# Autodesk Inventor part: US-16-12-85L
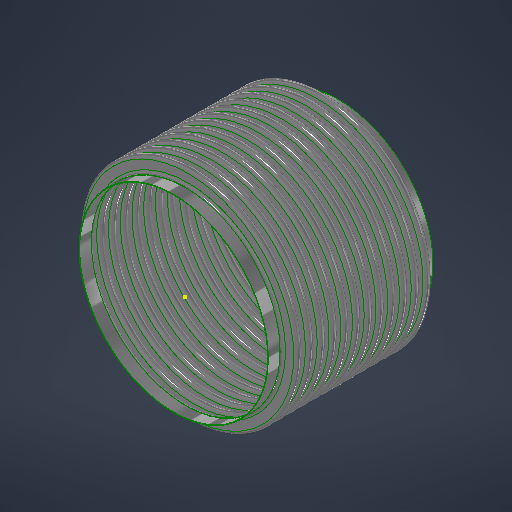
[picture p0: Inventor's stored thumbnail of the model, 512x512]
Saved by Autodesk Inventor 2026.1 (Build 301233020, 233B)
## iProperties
Category: 18 GA (0.048 THICK)
RuleStatus: InUse
Created: 2026-07
Part Number: US-16-12-85L
Project: =STOCK BELLOWS: <Stock Number><SFILL>
Material: ASTM A240-304
Description: =STOCK BELLOWS: <Stock Number>, <SID_> I.D., <SOD_> O.D., <SPLY_> PLY, <Category>, <SNET_CONS> CONS.<PITCH_><STANGENT_> TANGENT<SFILL>
Document SubType Name: Sheet Metal
Designer: LC
Stock Number: U.S-16-12-85L
Surface Area: 659.127 cm^2
Volume: 56.61 cm^3
Sheet Metal Rule: Default
Appearance: STAINLESS STEEL
NET_TUBE: 3.428
COUNTER: 1.500
PBAR: 1.214
PSET: 5.356
PLY: 2
CONS: 2
THK: 0.036
ID: 4.500
OD: 5.500
CONS_: 2
TANGENT: 0.500
PITCH: 0.375
BELLOWS_UPSET: 0.000
NET_CONS: 2
S_CONS: 0
Description_Units: 0
ID_M: 114.30 mm
OD_M: 139.70 mm
THK_M: 0.91 mm
ID_U: 4.500 in
OD_U: 5.500 in
THK_U: 0.036 in
TANGENT2: 0.500
d79: 1.000
d82: 1.000
d83: 26.000
d84: 24.000
d80: 2.571
d81: 10
SID: 2.375
SCONS_: 12
SPITCH: 0.250
SBELLOWS_UPSET: 0.000
SNET_CONS: 12
SS_CONS: 0
SCONS: 8
d174: 8
d177: 0.018
d178: 2.375
d179: 3.000
d180: 0.375
d181: 1.000
d182: 0.000
d190: 8
d191: 1
d192: 1
d193: 8
d194: 0
PART_NUMBER: U.S-16-12-85L
PRESSURE: 85
SIZE: 16.00
STANGENT_: 1.000
d214: 8
d217: 0.030
d218: 6.625
d219: 8.125
d220: 0.500
d221: 1.000
d222: 0.000
d230: 8
d231: 1
d232: 1
d233: 8
d234: 0
STANGENT: 4.000
SPLY_: 1
STHK_: 0.048
SID_: 16.000
SOD_: 18.500
SPITCH_: 1.000
STANGENT__: 1.000
SBELLOWS_UPSET_: 0.000
SDIFF_TAN: 1.000
TAN_TO_TAN: 0.750 in
d252: 2
d275: 2
d287: 0.050
d289: 0.500
d290: 0.000
d263: 2
d265: 1
d268: 2
d269: 0
d286: 2
d288: 1
d291: 2
d292: 0
SOD_NECK: 16 1/8
CFILL: .
SFILL: .
PITCH_: =, <SPITCH_> PITCH,
SREROLL: 0.750
MATTABLE: 20 GA (0.036 THICK)
MESH: ,
CSECT: 2
Author: LC
Keywords: 20 GA (0.036 THICK)
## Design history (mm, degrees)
sketch "Sketch2"
  geometry: L1 (0, -183.595)-(0, 600.956) reference; L2 (58.979, 0)-(57.15, 0); L3 (60.446, -1.467)-(66.554, -1.467); L4 (60.446, -3.296)-(66.554, -3.296); L5 (66.554, -8.058)-(60.446, -8.058); L6 (66.554, -6.229)-(60.446, -6.229); L7 (58.979, -9.525)-(57.15, -9.525); L8 (60.446, 0)-(60.446, -9.525); L9 (66.554, -4.762)-(69.85, -4.763); L10 (57.15, 0)-(57.15, -9.525); L11 (20.376, 102.841)-(20.376, 101.926); L12 (58.262, 488.877)-(58.262, 349.177); L13 (58.262, 479.352)-(58.262, 339.652); L14 (93.133, -58.817)-(93.133, -71.517); L15 (118.746, -66.401)-(118.746, -66.401); L16 (66.554, -6.229)-(66.554, -8.058); L17 (60.446, -6.229)-(60.446, -8.058); L18 (60.446, -7.144)-(66.554, -7.144); L19 (69.85, 0)-(69.85, -9.525); L20 (-66.554, -6.229)-(-66.554, -8.058); L21 (-66.554, -1.467)-(-60.446, -1.467); L22 (-66.554, -3.296)-(-60.446, -3.296); L23 (-60.446, -6.229)-(-66.554, -6.229); L24 (-66.554, -7.144)-(-60.446, -7.144); L25 (-60.446, -8.058)-(-66.554, -8.058); L26 (-60.446, -6.229)-(-60.446, -8.058); L27 (-57.15, -2.522)-(-57.15, -12.047); L28 (-60.446, -4.763)-(-57.15, -4.763); L29 (-66.554, 3.828)-(-66.554, -9.525); L30 (-68.021, 0)-(-69.85, 0); L31 (-69.85, 0)-(-69.85, -9.525); L32 (-68.021, -9.525)-(-69.85, -9.525); A1 r 1.467 centre (60.446, 0) between (58.979, 0) and (60.446, -1.467); A2 r 3.296 centre (60.446, 0) between (57.15, 0) and (60.446, -3.296); A3 r 3.296 centre (66.554, -4.762) between (66.554, -8.058) and (66.554, -1.467); A4 r 1.467 centre (66.554, -4.762) between (66.554, -6.229) and (66.554, -3.296); A5 r 1.467 centre (60.446, -9.525) between (60.446, -8.058) and (58.979, -9.525); A6 r 3.296 centre (60.446, -9.525) between (60.446, -6.229) and (57.15, -9.525); A7 r 2.381 centre (66.554, -4.762) between (66.554, -7.144) and (68.936, -4.762); A8 r 2.381 centre (60.446, -9.525) between (60.446, -7.144) and (58.064, -9.525); A9 r 1.467 centre (-66.554, -9.525) between (-66.554, -8.058) and (-68.021, -9.525); A10 r 1.467 centre (-60.446, -4.763) between (-60.446, -6.229) and (-60.446, -3.296); A11 r 2.381 centre (-60.446, -4.763) between (-60.446, -7.144) and (-58.064, -4.763); A12 r 3.296 centre (-60.446, -4.763) between (-60.446, -8.058) and (-60.446, -1.467); A13 r 2.381 centre (-66.554, -9.525) between (-66.554, -7.144) and (-68.936, -9.525); A14 r 3.296 centre (-66.554, -9.525) between (-66.554, -6.229) and (-69.85, -9.525); A15 r 1.467 centre (-66.554, 0) between (-68.021, 0) and (-66.554, -1.467); A16 r 3.296 centre (-66.554, 0) between (-69.85, 0) and (-66.554, -3.296); 10 further points
  constraints: 62 end point, 38 point on circle, 20 tangent, 16 centre point, 12 parallel, 9 midpoint, 7 vertical, 6 coincident, 6 concentric, 6 point on line, 4 equal radius, 4 perpendicular, 3 horizontal, 1 collinear, 1 horizontal alignment, 10 other
  dimensions: "THK" = 0.9144 distance of L11.start L11.end; "ID" = 114.3 distance of L11.end point (20.376, -12.374); "OD" = 139.7 distance of L12.start L12.end; "PITCH" = 9.525 distance of L12.start L13.start; "TANGENT" = 12.7 distance of L14.start L14.end; "BELLOWS_UPSET" = 0 distance of L15.start L15.end; "d43" = 114.3 diameter of L10 L1 (= ID); "d44" = 139.7 diameter of L9.end L1 (= OD); "d45" = 1.8288 distance between parallel lines of L5 L6 (computed from THK, PLY); "d46" = 3.29565 radius of A3 (computed from PITCH, THK, PLY); "UPSET_PITCH" = 9.525 distance of L2.end L7.end (derived); "SIDEWALL_ANGLE" = 0 deg angle of L3 L9 (derived); "CON_GAP" = 2.9337 distance of point (60.446, -6.229) point (60.446, -3.296) (derived); "TAN1" = 3.74046 dimension on A8 (derived); "TAN2" = 3.74046 dimension on A7 (derived); "LEG1" = 6.1087 distance of L18.start L18.end (derived); "d278" = 1.8288 distance between parallel lines of L25 L23 (derived); "d279" = 3.29565 radius of A12 (derived); "d280" = 9.525 distance of L30.end L31.end (derived); "d281" = 360 deg dimension on L21 L28 (derived); "d282" = 2.9337 distance of point (-66.554, -6.229) point (-66.554, -3.296) (derived); "d283" = 3.74046 dimension on A13 (derived); "d284" = 3.74046 dimension on A11 (derived); "d285" = 6.1087 distance of L24.start L24.end (derived); "d293" = 114.3 diameter of L27 L1 (derived); "d294" = 139.7 diameter of L31 L1 (derived)
  node "Sketch Rectangular Pattern1" dims "d31" = 25.4, "ID" = 114.3
  node "Sketch Rectangular Pattern2" dims "d39" = 25.4, "PITCH" = 9.525
revolve "CONS" stored, may be unused: angle "d48" = 90 deg
node "BELLOW MIDPLANE"
pattern_linear "Rectangular Pattern2" dims "d52" = 9.525 (= UPSET_PITCH)
sketch "Sketch5"
  geometry: C1 r 58.979 at (0, 0) reference; C2 r 57.15 at (0, 0) reference
extrude "TANGENT" new body sketch "Sketch5" distance "d53" = 12.7 (= TANGENT); taper "d54" = 0 deg
revolve "SAMETAN" stored, may be unused: angle "d65" = 90 deg
revolve "DIFFTAN" stored, may be unused: angle "d70" = 90 deg
sketch "Sketch9"
  geometry: L1 (58.391, 0)-(-58.391, 0) reference; L2 (0, -17.78)-(0, 17.78) reference; L3 (41.708, 0)-(-41.708, 0); L4 (41.708, -11.906)-(41.708, 11.906); L5 (29.008, -11.906)-(29.008, 11.906); L6 (15.418, 11.906)-(15.418, -11.906); L7 (-29.008, -11.906)-(-29.008, 11.906); L8 (-41.708, -11.906)-(-41.708, 11.906); L9 (40.914, -11.906)-(40.914, 11.906); L10 (41.708, -11.906)-(40.914, -11.906); L11 (41.708, 11.906)-(40.914, 11.906); L12 (15.815, 11.906)-(15.022, 11.906); L13 (15.022, 11.906)-(15.022, -11.906); L14 (15.022, -11.906)-(15.815, -11.906); L15 (15.815, -11.906)-(15.815, 11.906); L16 (-15.815, 11.906)-(-15.815, -11.906); L17 (-15.418, 11.906)-(-15.418, -11.906); L18 (-15.815, -11.906)-(-15.022, -11.906); L19 (-15.022, -11.906)-(-15.022, 11.906); L20 (-15.022, 11.906)-(-15.815, 11.906); L21 (-41.708, -11.906)-(-40.914, -11.906); L22 (-40.914, -11.906)-(-40.914, 11.906); L23 (-40.914, 11.906)-(-41.708, 11.906); L24 (-41.708, 11.906)-(-41.708, -11.906); L25 (41.708, -0.397)-(-41.708, -0.397); L26 (-41.708, -0.397)-(-41.708, 0.397); L27 (-41.708, 0.397)-(41.708, 0.397); L28 (41.708, 0.397)-(41.708, -0.397); L29 (-41.708, 11.906)-(41.708, 11.906); L30 (41.708, 11.906)-(41.708, 12.7); L31 (41.708, 12.7)-(-41.708, 12.7); L32 (-41.708, 12.7)-(-41.708, 11.906); L33 (41.708, -11.906)-(-41.708, -11.906); L34 (-41.708, -11.906)-(-41.708, -12.7); L35 (-41.708, -12.7)-(41.708, -12.7); L36 (41.708, -12.7)-(41.708, -11.906); 30 further points
  constraints: 68 end point, 13 midpoint, 13 parallel, 8 horizontal, 7 perpendicular, 6 equal length, 3 point on line, 2 vertical, 14 other
  dimensions: "d115" = 23.8125 distance of L4.start L4.end (derived); "d116" = 12.7 distance between parallel lines of L4 L5 (derived); "d117" = 13.58962 distance between parallel lines of L5 L6 (derived); "d125" = 44.42645 distance between parallel lines of L7 L6 (derived); "d127" = 12.7 distance between parallel lines of L8 L7 (derived); "d128" = 26.28962 distance between parallel lines of L6 L4 (derived); "d130" = 83.41607 distance between parallel lines of L8 L4 (derived); "RULER_THK" = 0.79375 distance between parallel lines of L4 L9; "d135" = 0.79375 distance of L13.end L14.end (derived); "d138" = 30.83684 distance of L13.end L16.end (derived); "d143" = 0.79375 distance of L22.end L8.end (derived); "d144" = 0.79375 distance between parallel lines of L27 L25 (derived)
extrude "RULER" join sketch "Sketch9" distance "d149" = 0.79375 (derived); taper "d150" = 0 deg
extrude "BARS" join sketch "Sketch9" distance "d151" = 0.79375 (derived); taper "d152" = 0 deg
pattern_linear "Rectangular Pattern4" dims "d155" = 30.83684 (derived)
sketch "Sketch13"
  geometry: L1 (93.149, -52.467)-(93.149, -77.867); L2 (204.419, 0)-(203.2, 0); L3 (204.419, -25.4)-(203.2, -25.4); L4 (227.99, -19.66)-(210.16, -19.66); L5 (227.99, -18.44)-(210.16, -18.44); L6 (227.99, -12.7)-(234.95, -12.7); L7 (210.16, -5.74)-(227.99, -5.74); L8 (210.16, 0)-(210.16, -25.4); L9 (203.2, 0)-(203.2, -25.4); L10 (58.254, -237.139)-(58.254, -707.039); L11 (58.254, -262.539)-(58.254, -732.439); L12 (58.254, -313.339)-(58.254, -783.239); L13 (58.254, -338.739)-(58.254, -808.639); L14 (58.254, -364.139)-(58.254, -834.039); L15 (58.254, -389.539)-(58.254, -859.439); L16 (58.254, -414.939)-(58.254, -884.839); L17 (58.254, -287.939)-(58.254, -757.839); L18 (20.376, 103.145)-(20.376, 101.926); L19 (210.16, -6.96)-(227.99, -6.96); L20 (0, -1034.115)-(0, 292.333) reference; L21 (-40.958, 0)-(245.745, 0) reference; A1 r 5.74 centre (210.16, 0) between (204.419, 0) and (210.16, -5.74); A2 r 5.74 centre (210.16, -25.4) between (210.16, -19.66) and (204.419, -25.4); A3 r 6.96 centre (210.16, -25.4) between (210.16, -18.44) and (203.2, -25.4); A4 r 5.74 centre (227.99, -12.7) between (227.99, -18.44) and (227.99, -6.96); A5 r 6.96 centre (227.99, -12.7) between (227.99, -19.66) and (227.99, -5.74); A6 r 6.96 centre (210.16, 0) between (203.2, 0) and (210.16, -6.96); 6 further points; 1 other entity
  constraints: 38 end point, 15 point on circle, 9 tangent, 6 centre point, 6 parallel, 5 vertical alignment, 4 point on line, 4 vertical, 3 coincident, 3 concentric, 2 collinear, 2 equal radius, 1 horizontal, 1 perpendicular, 23 other
  dimensions: "SBELLOWS_UPSET_" = 0 distance of point (118.762, -66.401) point (118.762, -66.401); "STOTAL_THK_BELLOW__" = 1.2192 distance between parallel lines of L4 L5 (derived); "d224" = 6.9596 radius of A5 (derived); "d225" = 25.4 distance of L2.end L3.end (derived); "SSIDEWALL_ANGLE_" = 0 deg angle of L7 L6 (derived); "SSCON_GAP_" = 11.4808 distance of point (210.16, -18.44) point (210.16, -6.96) (derived); "d235" = 406.4 diameter of L9 L20 (derived); "d236" = 469.9 diameter of L6.end L20 (derived)
  node "Sketch Rectangular Pattern4" dims "d228" = 25.4
  node "Sketch Rectangular Pattern5" dims "d229" = 25.4
revolve "SBELLOW" stored, may be unused: angle "d197" = 90 deg
pattern_linear "Rectangular Pattern5" dims "d204" = 25.4 (derived)
revolve "STANGENT" stored, may be unused: angle "d240" = 90 deg
revolve "SSAMETAN" stored, may be unused: angle "d241" = 90 deg
revolve "SDIFFTAN" stored, may be unused: angle "d246" = 90 deg
revolve "INVCON" stored, may be unused: angle "d295" = 90 deg
pattern_linear "Rectangular Pattern6" dims "d298" = 9.525 (derived)
revolve "INVTANGENT" stored, may be unused: angle "d302" = 90 deg
revolve "INVSAMETAN" stored, may be unused: angle "d307" = 90 deg
revolve "INVDIFFTAN" stored, may be unused: angle "d312" = 90 deg
sketch "ID BELLOW MOUNT CALC"
  geometry: L1 (44.45, 0)-(38.1, 0); L2 (38.1, 0)-(38.1, 12.7); L3 (38.1, 12.7)-(44.45, 12.7); L4 (44.45, 12.7)-(44.45, 0); L5 (36.513, 12.7)-(34.684, 12.7); L6 (34.684, 12.7)-(34.684, 0); L7 (34.684, 0)-(36.513, 0); L8 (36.513, 0)-(36.513, 12.7); L9 (0, -2.54)-(0, 15.24) reference; L10 (-8.89, 0)-(53.34, 0) reference; 1 further point
  constraints: 16 end point, 5 parallel, 2 collinear, 2 horizontal, 2 perpendicular
  dimensions: "d314" = 12.7 distance of L5.end L6.end (derived); "d315" = 1.8288 distance of L5.start L5.end (derived); "IG" = 1.5875 distance between parallel lines of L2 L8; "PIPE_OD" = 88.9 diameter of L4 L9; "PIPE_WALL" = 6.35 distance of L2.end L3.end; "ID_MT_BELLOW" = 69.3674 diameter of L6 L9 (derived)
revolve "CFILL" stored, may be unused: angle "d320" = 90 deg
pattern_linear "Rectangular Pattern7" dims "d323" = 9.525 (derived)
revolve "SFILL" stored, may be unused: angle "d324" = 90 deg
pattern_linear "Rectangular Pattern8" dims "d327" = 25.4 (derived)
node "STOCK BELLOW MIDPLANE"
sketch "Sketch21"
  geometry: L1 (0, -100.013)-(0, 100.013) reference; L2 (-100.013, 0)-(100.013, 0) reference; L3 (-0.099, 71.437)-(0.099, 71.437); L4 (0.099, 71.437)-(0.099, 55.562); L5 (0.099, 55.562)-(-0.099, 55.562); L6 (-0.099, 55.562)-(-0.099, 71.437); C1 r 55.562 at (0, 0); C2 r 71.437 at (0, 0); 3 further points
  constraints: 8 end point, 2 centre point, 2 coincident, 2 parallel, 2 tangent, 1 horizontal, 1 perpendicular, 1 other
  dimensions: "d329" = 111.125 diameter of C1 (derived); "d330" = 142.875 diameter of C2 (derived); "d331" = 0.19844 distance of L3.start L3.end
extrude "CLAMSHELL" cut sketch "Sketch21" extent not by distance; stored distance "d332" = 0; taper "d333" = 0 deg
pattern_circular "Circular Pattern1" dims angle "d335" = 180 deg (derived)
node "BELLOW"
sketch "Sketch6"
  geometry: L1 (-19.05, 58.979)-(-6.35, 58.979); L2 (-6.35, 58.979)-(-6.35, 57.15); L3 (-6.35, 57.15)-(-19.05, 57.15); L4 (-19.05, 57.15)-(-19.05, 58.979); L5 (2.54, 0)-(-59.69, 0) reference; L6 (-38.1, -108.388)-(-38.1, 156.601) reference; 1 further point
  constraints: 8 end point, 2 parallel, 1 horizontal, 1 perpendicular
  dimensions: "d61" = 12.7 distance of L2.end L3.end (derived); "d62" = 1.8288 distance of L1.end L2.end (derived); "d63" = 114.3 diameter of L3 L5 (derived); "d64" = 19.05 distance between parallel lines of L4 L6 (derived)
sketch "Sketch12"
  geometry: 1 further point
sketch "Sketch14"
  geometry: L1 (-25.4, 204.419)-(0, 204.419); L2 (0, 204.419)-(0, 203.2); L3 (0, 203.2)-(-25.4, 203.2); L4 (-25.4, 203.2)-(-25.4, 204.419); L5 (5.08, 0)-(-30.48, 0) reference; L6 (0, -35.743)-(0, 214.457) reference; 1 further point
  constraints: 8 end point, 2 parallel, 1 collinear, 1 horizontal, 1 perpendicular
  dimensions: "d237" = 1.2192 distance of L3.end L1.start (derived); "d238" = 406.4 diameter of L3 L5 (derived); "d239" = 25.4 distance of L1.start L1.end (derived); "SOD_NECK" = 408.8384 diameter of L1 L5 (derived)
sketch "Sketch15"
  geometry: L1 (-35.743, 0)-(214.457, 0) reference; L2 (203.2, -304.8)-(204.419, -304.8); L3 (204.419, -304.8)-(204.419, -330.2); L4 (204.419, -330.2)-(203.2, -330.2); L5 (203.2, -330.2)-(203.2, -304.8); L6 (0, -398.78)-(0, 81.28) reference; 1 further point
  constraints: 8 end point, 2 parallel, 1 horizontal, 1 perpendicular
  dimensions: "d205" = 25.4 distance of L4.end L2.start (derived); "d206" = 1.2192 distance of L3.end L4.end (derived); "d207" = 406.4 diameter of L5 L6 (derived); "d208" = 304.8 distance between parallel lines of L1 L2 (derived)
node "TANGENT_"
node "SAME_TAN"
sketch "Sketch8"
  geometry: L1 (58.979, -19.05)-(57.15, -19.05); L2 (57.15, -19.05)-(57.15, -31.75); L3 (57.15, -31.75)-(58.979, -31.75); L4 (58.979, -31.75)-(58.979, -19.05); L5 (0, -40.64)-(0, 21.59) reference; L6 (-108.388, 0)-(156.601, 0) reference; 1 further point
  constraints: 8 end point, 2 parallel, 1 horizontal, 1 perpendicular
  dimensions: "d66" = 114.3 diameter of L2 L5 (derived); "TOTAL_THK_BELLOW" = 1.8288 distance of L2.end L3.end (derived); "d68" = 19.05 distance between parallel lines of L1 L6 (derived); "d69" = 12.7 distance of L1.end L2.end (derived)
node "DIFF_TAN"
node "Sketch Rectangular Pattern3" dims "d138" = 30.83684 (derived), "d141" = 25.4
node "SBELLOW_"
node "STANGENT_"
node "SSAME_TAN"
sketch "Sketch16"
  geometry: L1 (204.419, -304.8)-(203.2, -304.8); L2 (203.2, -304.8)-(203.2, -330.2); L3 (203.2, -330.2)-(204.419, -330.2); L4 (204.419, -330.2)-(204.419, -304.8); L5 (0, -398.78)-(0, 81.28) reference; L6 (-35.743, 0)-(214.457, 0) reference; 1 further point
  constraints: 8 end point, 2 parallel, 1 horizontal, 1 perpendicular
  dimensions: "SDIFF_TAN" = 25.4 distance of L3.end L1.start; "d243" = 1.2192 distance of L2.end L3.end (derived); "d244" = 304.8 distance between parallel lines of L1 L6 (derived); "d245" = 406.4 diameter of L2 L5 (derived)
node "SDIFF_TAN"
body "Solid15"
sketch "Sketch17"
  geometry: L1 (69.85, 12.7)-(68.021, 12.7); L2 (68.021, 12.7)-(68.021, 0); L3 (68.021, 0)-(69.85, 0); L4 (69.85, 0)-(69.85, 12.7); L5 (0, -2.54)-(0, 15.24) reference; L6 (-13.97, 0)-(83.82, 0) reference; 2 further points
  constraints: 8 end point, 2 parallel, 1 horizontal, 1 midpoint, 1 perpendicular, 1 point on line
  dimensions: "INVTANGENT" = 12.7 distance of L3.end L1.start (derived); "d300" = 1.8288 distance of L1.start L1.end (derived); "d301" = 139.7 diameter of L4 L5 (derived)
body "Solid16"
sketch "Sketch18"
  geometry: L1 (69.85, -19.05)-(68.021, -19.05); L2 (68.021, -19.05)-(68.021, -31.75); L3 (68.021, -31.75)-(69.85, -31.75); L4 (69.85, -31.75)-(69.85, -19.05); L5 (-13.97, 0)-(83.82, 0) reference; L6 (0, -40.64)-(0, 21.59) reference; 1 further point
  constraints: 8 end point, 2 parallel, 1 horizontal, 1 perpendicular
  dimensions: "d303" = 19.05 distance between parallel lines of L1 L5 (derived); "d304" = 12.7 distance of L3.end L1.start (derived); "d305" = 1.8288 distance of L2.end L3.end (derived); "d306" = 139.7 diameter of L4 L6 (derived)
body "Solid17"
sketch "Sketch19"
  geometry: L1 (69.85, -19.05)-(68.021, -19.05); L2 (68.021, -19.05)-(68.021, -31.75); L3 (68.021, -31.75)-(69.85, -31.75); L4 (69.85, -31.75)-(69.85, -19.05); L5 (0, -40.64)-(0, 21.59) reference; L6 (-13.97, 0)-(83.82, 0) reference; 1 further point
  constraints: 8 end point, 2 parallel, 1 horizontal, 1 perpendicular
  dimensions: "d308" = 12.7 distance of L1.end L2.end (derived); "d309" = 139.7 diameter of L4 L5 (derived); "d310" = 1.8288 distance of L2.end L3.end (derived); "d311" = 19.05 distance between parallel lines of L1 L6 (derived)
body "Solid18"
body "Solid19"
body "Solid20"
other parameters: "BMPL" = -152.4, "PSET" = 136.0424 (computed from OD, THK, PLY) [user parameter], "PBAR" = 30.83684 (= 0.570796 x PITCH + OD - ID) [user parameter; used in 1 equation term], "COUNTER" = 15 [user parameter], "NET_TUBE" = 87.07367 (computed from CONS_, PBAR, TANGENT) [user parameter], "S_CONS" = 0 [user parameter; used in 1 equation term], "ID_M" = 114.3 (= ID) [user parameter], "OD_M" = 139.7 (= OD) [user parameter], "THK_M" = 0.9144 (= THK) [user parameter], "ID_U" = 114.3 (= ID) [user parameter], "OD_U" = 139.7 (= OD) [user parameter], "THK_U" = 0.9144 (= THK) [user parameter], "D_UNITS" = 0 [user parameter], "TANGENT2" = 12.7 [user parameter], "TAN_TO_TAN" = 19.05 [user parameter], "OD_NECK" = 117.9576 [user parameter], "d79" = 25.4, "d80" = 65.29823 [user parameter], "d82" = 25.4, "d83" = 660.4, "d84" = 609.6, "sa_0" = 4, "FRAME_THK" = 0.79375 [user parameter], "CON_FLAT" = 13.58962 [user parameter], "SID" = 60.325 [user parameter], "SPITCH" = 6.35 [user parameter], "STANGENT_" = 25.4 [user parameter], "SBELLOWS_UPSET" = 0 [user parameter], "SS_CONS" = 0 [user parameter], "STAN_TO_TAN_" = 304.8 [user parameter], "d100" = 1.2192 [user parameter], "d191" = 25.4 [user parameter], "d194" = 0 [user parameter], "STANGENT" = 101.6 [user parameter], "d234" = 0 [user parameter], "SUPSET_PITCH_" = 25.4 [user parameter], "d269" = 0 [user parameter], "d287" = 1.27, "d289" = 12.7, "d290" = 0, "d292" = 0 [user parameter], "Thickness" = 3.048 (derived), "KFactor" = 4.4, "BendRadius" = 3.048 (derived), "BendReliefWidth" = 3.048 (derived), "BendReliefDepth" = 1.524 (derived), "CornerReliefSize" = 12.192 (derived), "SeamGap" = 0.00508, "MinimumRemnant" = 6.096 (derived), "TransitionRadius" = 3.048 (derived), "JacobiRadiusSize" = 3.048 (derived), "GapSize" = 3.048 (derived), "SREROLL" = 19.05 [user parameter], "CUR_STK_PITCH" = 25.4 [user parameter], "d328" = -152.4 (derived), "CSECTDEG" = 180 deg [user parameter]
